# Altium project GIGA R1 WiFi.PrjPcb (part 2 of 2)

## Sheet Wifi.SchDoc: WIFI / BLE
size A4; Author: Silvio Navaretti; CompanyName: Arduino srl; DocumentNumber: ABX00063; Revision: V1.4; SheetNumber: 6; SheetTotal: 8; RevAuthor: Silvio Navaretti
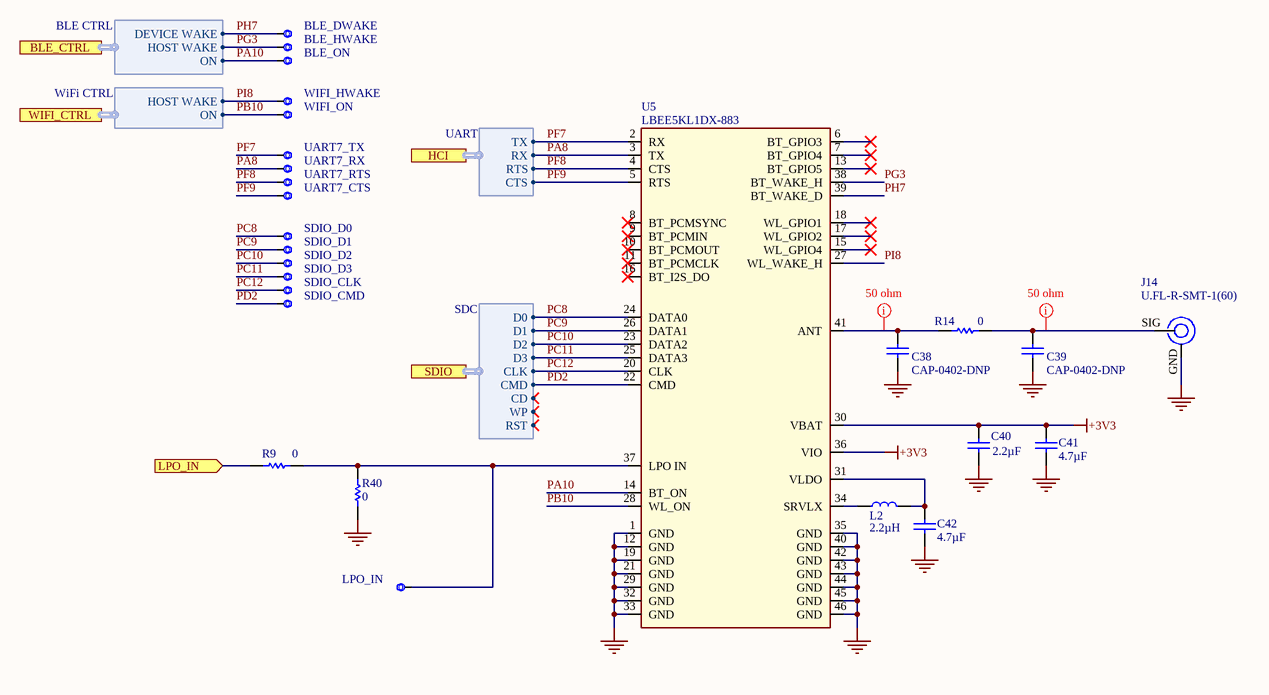
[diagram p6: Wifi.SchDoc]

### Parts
BLE_DWAKE  CMP-018-0005-A.3  [TP-1.00MM]  (value not drawn)  (no BOM)
BLE_HWAKE  CMP-018-0005-A.3  [TP-1.00MM]  (value not drawn)  (no BOM)
BLE_ON  CMP-018-0005-A.3  [TP-1.00MM]  (value not drawn)  (no BOM)
C38  CAP-0402-DNP  [CAP-0402]
C39  CAP-0402-DNP  [CAP-0402]
C40  value 2.2µF  [CAP-0402]  (hidden comment: GRM155R60J225KE95D)
C41  value 4.7µF  [CAP-0402]  (hidden comment: C1005A475M6R3NT)
C42  value 4.7µF  [CAP-0402]  (hidden comment: C1005A475M6R3NT)
J14  U.FL-R-SMT-1(60)  [U.FL-R-SMT-1(60)-1]
L2  value 2.2µH  [FP-LQM18PN_GH-IPC_C]  (hidden comment: LQM18PN2R2MGHD)
LPO_IN  CMP-018-0005-A.3  [TP-1.00MM]  (value not drawn)  (no BOM)
R9  value 0  [RES-0402]  (hidden comment: CRCW04020000Z0EDC)
R14  value 0  [RES-0402]  (hidden comment: CRCW04020000Z0EDC)
R40  value 0  [RES-0402]  (hidden comment: CRCW04020000Z0EDC)
SDIO_CLK  CMP-018-0005-A.3  [TP-1.00MM]  (value not drawn)  (no BOM)
SDIO_CMD  CMP-018-0005-A.3  [TP-1.00MM]  (value not drawn)  (no BOM)
SDIO_D0  CMP-018-0005-A.3  [TP-1.00MM]  (value not drawn)  (no BOM)
SDIO_D1  CMP-018-0005-A.3  [TP-1.00MM]  (value not drawn)  (no BOM)
SDIO_D2  CMP-018-0005-A.3  [TP-1.00MM]  (value not drawn)  (no BOM)
SDIO_D3  CMP-018-0005-A.3  [TP-1.00MM]  (value not drawn)  (no BOM)
U5  LBEE5KL1DX-883  [LBEE5KL1DX-883]
UART7_CTS  CMP-018-0005-A.3  [TP-1.00MM]  (value not drawn)  (no BOM)
UART7_RTS  CMP-018-0005-A.3  [TP-1.00MM]  (value not drawn)  (no BOM)
UART7_RX  CMP-018-0005-A.3  [TP-1.00MM]  (value not drawn)  (no BOM)
UART7_TX  CMP-018-0005-A.3  [TP-1.00MM]  (value not drawn)  (no BOM)
WIFI_HWAKE  CMP-018-0005-A.3  [TP-1.00MM]  (value not drawn)  (no BOM)
WIFI_ON  CMP-018-0005-A.3  [TP-1.00MM]  (value not drawn)  (no BOM)

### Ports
BLE_CTRL (harness BLE CTRL), HCI (harness UART), LPO_IN (in), SDIO (harness SDC), WIFI_CTRL (harness WiFi CTRL)

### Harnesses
BLE CTRL: HOST WAKE, DEVICE WAKE, ON
UART: RX, TX, RTS, CTS
WiFi CTRL: HOST WAKE, ON
SDC: CLK, CMD, D0, D1, D2, D3, CD, WP, RST

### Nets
+3V3: C40.2 C41.1 U5.30(VBAT) U5.36(VIO)
GND: C38.2 C39.2 C40.1 C41.2 C42.2 J14.GND R40.1 U5.1(GND) U5.12(GND) U5.19(GND) U5.21(GND) U5.29(GND) U5.32(GND) U5.33(GND) U5.35(GND) U5.40(GND) U5.42(GND) U5.43(GND) U5.44(GND) U5.45(GND) U5.46(GND)
MEMS_32.768kHz: R9.1 ; port LPO_IN
PA8: U5.3(TX) UART7_RX.X ; port HCI.RX
PA10: BLE_ON.X U5.14(BT_ON) ; port BLE_CTRL.ON
PB10: U5.28(WL_ON) WIFI_ON.X ; port WIFI_CTRL.ON
PC8: SDIO_D0.X U5.24(DATA0) ; port SDIO.D0
PC9: SDIO_D1.X U5.26(DATA1) ; port SDIO.D1
PC10: SDIO_D2.X U5.23(DATA2) ; port SDIO.D2
PC11: SDIO_D3.X U5.25(DATA3) ; port SDIO.D3
PC12: SDIO_CLK.X U5.20(CLK) ; port SDIO.CLK
PD2: SDIO_CMD.X U5.22(CMD) ; port SDIO.CMD
PF7: U5.2(RX) UART7_TX.X ; port HCI.TX
PF8: U5.4(CTS) UART7_RTS.X ; port HCI.RTS
PF9: U5.5(RTS) UART7_CTS.X ; port HCI.CTS
PG3: BLE_HWAKE.X U5.38(BT_WAKE_H) ; port BLE_CTRL.HOST WAKE
PH7: BLE_DWAKE.X U5.39(BT_WAKE_D) ; port BLE_CTRL.DEVICE WAKE
PI8: U5.27(WL_WAKE_H) WIFI_HWAKE.X ; port WIFI_CTRL.HOST WAKE
NetC38_1: C38.1 R14.1 U5.41(ANT)
NetC39_1: C39.1 J14.SIG R14.2
NetC42_1: C42.1 L2.2 U5.31(VLDO)
NetL2_1: L2.1 U5.34(SRVLX)
NetLPO_IN_X: LPO_IN.X R9.2 R40.2 U5.37(LPO_IN)

Not connected (* = marked no-connect by the designer): U5 6(BT_GPIO3)* 7(BT_GPIO4)* 8(BT_PCMSYNC)* 9(BT_PCMIN)* 10(BT_PCMOUT)* 11(BT_PCMCLK)* 13(BT_GPIO5)* 15(WL_GPIO4)* 16(BT_I2S_DO)* 17(WL_GPIO2)* 18(WL_GPIO1)*

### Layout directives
net class 50 ohm: NetC38_1, NetC39_1

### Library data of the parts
BLE_DWAKE BLE_HWAKE BLE_ON LPO_IN SDIO_CLK SDIO_CMD SDIO_D0-SDIO_D3 UART7_CTS UART7_RTS UART7_RX UART7_TX WIFI_HWAKE WIFI_ON = UT0013-A.4: Test point 1.00mm
C38 C39 = UT0021-A.3: DNP CAP 0402
C40 = C0031-A.14: CAP CHIP 0402 2.2uF 10% 6.3V X5R; Manufacturer: Murata; Code Arduino: A5529
C41 C42 = C0037-A.14: CAP CHIP 0402 4.7uF 20% 6V3 X5R; Manufacturer: Hottech; Code Arduino: 0833; Voltage: 6.3V
J14 = J0045-A.8: CONN Micro UFL; Manufacturer: Hirose; Code Arduino: A5364
L2 = I0051-A.5: IND FIXED SMD 0603 2.2uH, 20%,; Manufacturer: Murata; Code Arduino: I0051; Test Frequency: 1MHz; DC Resistance (DCR): 250mR
R9 R40 = R0000-A.23: RES CHIP 0402 0R 1/16W; Manufacturer: Vishay; Power: 62.5mW; Tolerance: 0%; Code Arduino: 0039; Temperature coefficient: 0ppm
R14 = R0000-A.23: RES CHIP 0402 0R 1/16W; Manufacturer: Vishay; Code Arduino: 0039; Tolerance: 0%; Power: 62.5mW; Temperature coefficient: 0ppm
U5 = U0008-A.17: MODULE WiFi 11b/g/n+BLUETOOTH 4.2 SHIELDED ULTRA SMALL LBEE5KL1DX; Manufacturer: Murata; Code Arduino: U0008

## Sheet CRYPTOCHIP.SchDoc: CRYPTO
size A4; Author: Silvio Navaretti; CompanyName: Arduino srl; DocumentNumber: ABX00063; Revision: V1.4; SheetNumber: 8; SheetTotal: 8; RevAuthor: Silvio Navaretti
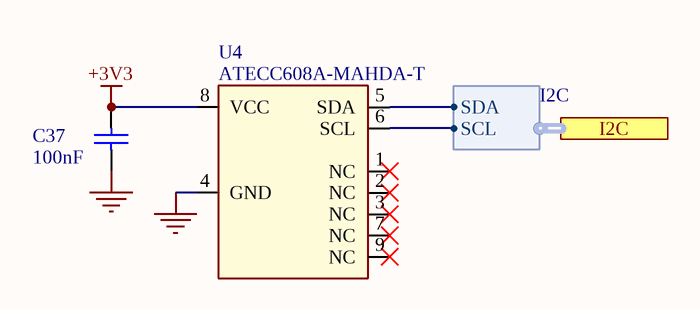
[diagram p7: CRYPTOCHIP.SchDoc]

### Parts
C37  value 100nF  [CAP-0402]  (hidden comment: GRM155R61H104KE19D)
U4  ATECC608A-MAHDA-T  [UDFN8]

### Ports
I2C (harness I2C)

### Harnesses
I2C: SDA, SCL

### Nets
+3V3: C37.2 U4.8(VCC)
GND: C37.1 U4.4(GND)
I2C4.SCL: U4.6(SCL) ; port I2C.SCL
I2C4.SDA: U4.5(SDA) ; port I2C.SDA

Not connected (* = marked no-connect by the designer): U4 1(NC)* 2(NC)* 3(NC)* 7(NC)* 9(NC)*

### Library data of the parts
C37 = C0015-A.14: CAP CHIP 0402 100nF 10% 50V X5R; Manufacturer: Murata; Code Arduino: A5141
U4 = U0034-A.8: IC AUTHENTICATION CHIP UDFN8; Manufacturer: Microchip; Code Arduino: U0034

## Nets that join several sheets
+3V3: TOP (DL1.A DL2.4 PB2.2), POWER (R39.2), STM32H747 (83 pins), HEADERS (7 pins), Wifi (C40.2 C41.1 U5.30 U5.36), CRYPTOCHIP (C37.2 U4.8)
+5V: POWER (6 pins), USB (D1.C U9.A1 U9.B1), HEADERS (6 pins)
GND: TOP (PB1.1 R10.1), AUDIO (C55.1 C56.1 J15.1 R23.1), POWER (19 pins), USB (16 pins), STM32H747 (111 pins), HEADERS (20 pins), Wifi (21 pins), CRYPTOCHIP (C37.1 U4.4)
VIN: POWER (5 pins), HEADERS (J5.24 JANALOG.8)
DSI_CK_N: STM32H747 (U1.L17), HEADERS (DSI_CK_N.X J5.5)
DSI_CK_P: STM32H747 (U1.L16), HEADERS (DSI_CK_P.X J5.6)
DSI_D0_N: STM32H747 (U1.M17), HEADERS (DSID0N.X J5.9)
DSI_D0_P: STM32H747 (U1.M16), HEADERS (DSI_D0_P.X J5.10)
DSI_D1_N: STM32H747 (U1.K17), HEADERS (DSI_D1_N.X J5.1)
DSI_D1_P: STM32H747 (U1.K16), HEADERS (DSI_D1_P.X J5.2)
I2C4.SCL: STM32H747 (R26.1 U1.B5), HEADERS (J6.3 JDIGITAL.1 SCL4.X), CRYPTOCHIP (U4.6)
I2C4.SDA: STM32H747 (R27.1 U1.R14), HEADERS (J6.4 JDIGITAL.2 SDATA.X), CRYPTOCHIP (U4.5)
JTAG.~{RESET}: TOP (PB1.2), STM32H747 (R21.2 U1.K1), HEADERS (J7.5 J8.10 JANALOG.3 JTAG_NRST.X)
JTAG.TCK/SCK: STM32H747 (U1.B14), HEADERS (J8.4 JTAG_TCK_SCK.X)
JTAG.TMS/SWD: STM32H747 (U1.C15), HEADERS (J8.2 JTAG_TMS/SWD.X)
LEFT: AUDIO (R25.1), STM32H747 (U1.T3), HEADERS (JANALOG.22)
MEMS_32.768kHz: STM32H747 (C72.1 R6.2 Y1.2), Wifi (R9.1)
MIC: AUDIO (C4.2 R22.1 R23.2), STM32H747 (U1.N5), HEADERS (JANALOG.16)
Net3V3_EN_X: POWER (3V3_EN.X R30.2 U6.3), HEADERS (J1.1)
NetJ1_3: STM32H747 (U1.B1), HEADERS (J1.3)
NetJDIGITAL_3: STM32H747 (R7.1 U1.M1), HEADERS (JDIGITAL.3)
PA0_C: STM32H747 (U1.T1), HEADERS (JANALOG.20)
PA1: STM32H747 (U1.N4), HEADERS (J6.17 J6.19 POWER_EN.X)
PA1_C: STM32H747 (U1.T2), HEADERS (JANALOG.19)
PA2: STM32H747 (U1.N3), HEADERS (JDIGITAL.15)
PA3: STM32H747 (U1.U2), HEADERS (JDIGITAL.16)
PA4: AUDIO (R24.1), STM32H747 (U1.U3), HEADERS (JANALOG.21)
PA6: STM32H747 (U1.R3), HEADERS (J6.7 PCLK.X)
PA7: STM32H747 (U1.R5), HEADERS (JDIGITAL.13)
PA8: STM32H747 (U1.E15), Wifi (U5.3 UART7_RX.X)
PA9: STM32H747 (U1.D15), HEADERS (JDIGITAL.17)
PA10: STM32H747 (U1.D14), Wifi (BLE_ON.X U5.14)
PA15: USB (U9.C3), STM32H747 (U1.A14)
PB0: STM32H747 (U1.U5), HEADERS (JANALOG.11)
PB1: STM32H747 (U1.T5), HEADERS (JANALOG.12)
PB2: STM32H747 (U1.R6), HEADERS (JSIDE.28)
PB3: STM32H747 (U1.C6), HEADERS (J7.3)
PB4: STM32H747 (U1.B7), HEADERS (JDIGITAL.11)
PB5: STM32H747 (U1.A5), HEADERS (JANALOG.23)
PB7: STM32H747 (U1.C5), HEADERS (JDIGITAL.18)
PB8: STM32H747 (R29.1 U1.D5), HEADERS (JDIGITAL.10)
PB9: STM32H747 (R28.1 U1.D4), HEADERS (JDIGITAL.9)
PB10: STM32H747 (U1.P11), Wifi (U5.28 WIFI_ON.X)
PB11: STM32H747 (R19.1 U1.P12), HEADERS (JDIGITAL.25)
PB12: STM32H747 (U1.T14), HEADERS (J5.19 PB12.X)
PB13: STM32H747 (U1.U14), HEADERS (JANALOG.24)
PC0: STM32H747 (U1.L2), HEADERS (JANALOG.15)
PC1: STM32H747 (U1.M2), HEADERS (DFSDM1_DATIN0.X J5.18)
PC2: STM32H747 (U1.M3), HEADERS (JANALOG.14)
PC2_C: STM32H747 (U1.R1), HEADERS (JANALOG.17)
PC3: STM32H747 (U1.M4), HEADERS (JANALOG.13)
PC3_C: STM32H747 (U1.R2), HEADERS (JANALOG.18)
PC4: STM32H747 (U1.T4), HEADERS (JANALOG.9)
PC5: STM32H747 (U1.U4), HEADERS (JANALOG.10)
PC6: STM32H747 (U1.F14), HEADERS (I2S2_MCK.X J5.13)
PC7: STM32H747 (U1.F13), HEADERS (JDIGITAL.20)
PC8: STM32H747 (U1.E13), Wifi (SDIO_D0.X U5.24)
PC9: STM32H747 (U1.E14), Wifi (SDIO_D1.X U5.26)
PC10: STM32H747 (U1.A13), Wifi (SDIO_D2.X U5.23)
PC11: STM32H747 (U1.B13), Wifi (SDIO_D3.X U5.25)
PC12: STM32H747 (U1.C12), Wifi (SDIO_CLK.X U5.20)
PC13: TOP (BOOT0/PC13.X PB2.1), STM32H747 (R4.1 U1.E3 U1.E8)
PD2: STM32H747 (U1.D12), Wifi (SDIO_CMD.X U5.22)
PD3: STM32H747 (U1.B12), HEADERS (DFSDM1_CKOUT.X J5.20)
PD4: STM32H747 (U1.A12), HEADERS (J6.18 J6.20 PWDN.X)
PD5: STM32H747 (U1.A11), HEADERS (JDIGITAL.23)
PD6: STM32H747 (U1.B11), HEADERS (JDIGITAL.24)
PD7: STM32H747 (U1.C11), HEADERS (J7.4)
PD13: STM32H747 (U1.R17), HEADERS (JDIGITAL.12)
PE3: TOP (BLUE.X R12.2), STM32H747 (U1.D3)
PE4: STM32H747 (U1.D2), HEADERS (JSIDE.30)
PE5: STM32H747 (U1.D1), HEADERS (JSIDE.32)
PE6: STM32H747 (U1.E5), HEADERS (JSIDE.21)
PF7: STM32H747 (U1.K3), Wifi (U5.2 UART7_TX.X)
PF8: STM32H747 (U1.K4), Wifi (U5.4 UART7_RTS.X)
PF9: STM32H747 (U1.L4), Wifi (U5.5 UART7_CTS.X)
PG3: STM32H747 (U1.H15), Wifi (BLE_HWAKE.X U5.38)
PG7: STM32H747 (U1.F16), HEADERS (JSIDE.34)
PG9: STM32H747 (U1.A10), HEADERS (J7.1)
PG10: STM32H747 (U1.A9), HEADERS (JSIDE.25)
PG11: STM32H747 (U1.B9), HEADERS (DOUT3.X J6.13)
PG12: STM32H747 (U1.C9), HEADERS (JSIDE.5)
PG13: STM32H747 (U1.D9), HEADERS (JSIDE.4)
PG14: STM32H747 (U1.D8), HEADERS (JDIGITAL.19)
PH4: STM32H747 (R20.1 U1.P3), HEADERS (JDIGITAL.26)
PH6: STM32H747 (U1.T11), HEADERS (JDIGITAL.5)
PH7: STM32H747 (U1.U13), Wifi (BLE_DWAKE.X U5.39)
PH8: STM32H747 (U1.T13), HEADERS (HREF.X J6.6)
PH9: STM32H747 (U1.R13), HEADERS (DOUT0.X J6.16)
PH10: STM32H747 (U1.P13), HEADERS (DOUT1.X J6.15)
PH11: STM32H747 (U1.P14), HEADERS (DOUT2.X J6.14)
PH13: STM32H747 (U1.D16), HEADERS (JDIGITAL.21)
PH14: STM32H747 (U1.B17), HEADERS (DOUT4.X J6.12)
PH15: STM32H747 (U1.B16), HEADERS (JSIDE.27)
PI0: STM32H747 (U1.A16), HEADERS (I2S2_WS.X J5.14)
PI1: STM32H747 (U1.A15), HEADERS (I2S2_CK.X J5.15)
PI2: STM32H747 (U1.B15), HEADERS (IS2S_SDI.X J5.16)
PI3: STM32H747 (U1.C14), HEADERS (I2S2_SDO.X J5.17)
PI4: STM32H747 (U1.A4), HEADERS (DOUT5.X J6.11)
PI5: STM32H747 (U1.A3), HEADERS (J6.5 VSYNC.X)
PI6: STM32H747 (U1.A2), HEADERS (DOUT6.X J6.10)
PI7: STM32H747 (U1.B3), HEADERS (DOUT7.X J6.9)
PI8: STM32H747 (U1.E4), Wifi (U5.27 WIFI_HWAKE.X)
PI9: STM32H747 (U1.E2), HEADERS (JDIGITAL.22)
PI10: STM32H747 (U1.F3), HEADERS (JSIDE.24)
PI11: STM32H747 (U1.F4), HEADERS (JSIDE.31)
PI12: TOP (R11.2 RED.X), STM32H747 (U1.H1)
PI13: STM32H747 (U1.H2), HEADERS (JSIDE.26)
PI14: STM32H747 (U1.H3), HEADERS (JSIDE.20)
PI15: STM32H747 (U1.P5), HEADERS (JSIDE.23)
PJ0: STM32H747 (U1.N6), HEADERS (JSIDE.6)
PJ1: STM32H747 (U1.P6), HEADERS (JSIDE.8)
PJ2: STM32H747 (U1.T6), HEADERS (JSIDE.10)
PJ3: STM32H747 (U1.U6), HEADERS (JSIDE.12)
PJ4: STM32H747 (U1.U7), HEADERS (JSIDE.14)
PJ5: STM32H747 (U1.R12), HEADERS (JSIDE.16)
PJ6: STM32H747 (U1.N15), HEADERS (JSIDE.18)
PJ7: STM32H747 (U1.N14), HEADERS (JSIDE.19)
PJ8: STM32H747 (U1.N13), HEADERS (JDIGITAL.14)
PJ9: STM32H747 (U1.M14), HEADERS (J6.8 XCLK.X)
PJ10: STM32H747 (U1.L14), HEADERS (JDIGITAL.7)
PJ11: STM32H747 (U1.K14), HEADERS (JDIGITAL.6)
PJ12: STM32H747 (U1.D11), HEADERS (JSIDE.3)
PJ13: TOP (GREEN.X R13.2), STM32H747 (U1.E10)
PJ14: STM32H747 (U1.D10), HEADERS (JSIDE.7)
PJ15: STM32H747 (U1.B10), HEADERS (JSIDE.9)
PK0: STM32H747 (U1.J14), HEADERS (JSIDE.29)
PK1: STM32H747 (U1.J15), HEADERS (JDIGITAL.8)
PK2: STM32H747 (U1.H17), HEADERS (JSIDE.33)
PK3: STM32H747 (U1.C8), HEADERS (JSIDE.11)
PK4: STM32H747 (U1.B8), HEADERS (JSIDE.13)
PK5: STM32H747 (U1.A8), HEADERS (JSIDE.15)
PK6: STM32H747 (U1.C7), HEADERS (JSIDE.17)
PK7: STM32H747 (U1.D7), HEADERS (JSIDE.22)
USB0_D_N: USB (D2.3 J12.A7 J12.B7 USB0_DN.X), STM32H747 (U1.E17)
USB0_D_P: USB (D2.2 J12.A6 J12.B6 USB0_DP.X), STM32H747 (U1.E16)
USB1_D_N: USB (D4.3 J2.2 USB1_DN.X), STM32H747 (U1.U15)
USB1_D_P: USB (D4.2 J2.3 USB1_DP.X), STM32H747 (U1.T15)

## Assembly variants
ABX00063 GIGA WiFi R1: not fitted C4 C12 C13 C14 C15 C16 C17 C21 C22 C23 C24 C25 C26 C30 C31 C38 C39 C51 C52 C53 C54 C55 C56 C57 C72 R6 R9 R23 R28 R29 R36 Y1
